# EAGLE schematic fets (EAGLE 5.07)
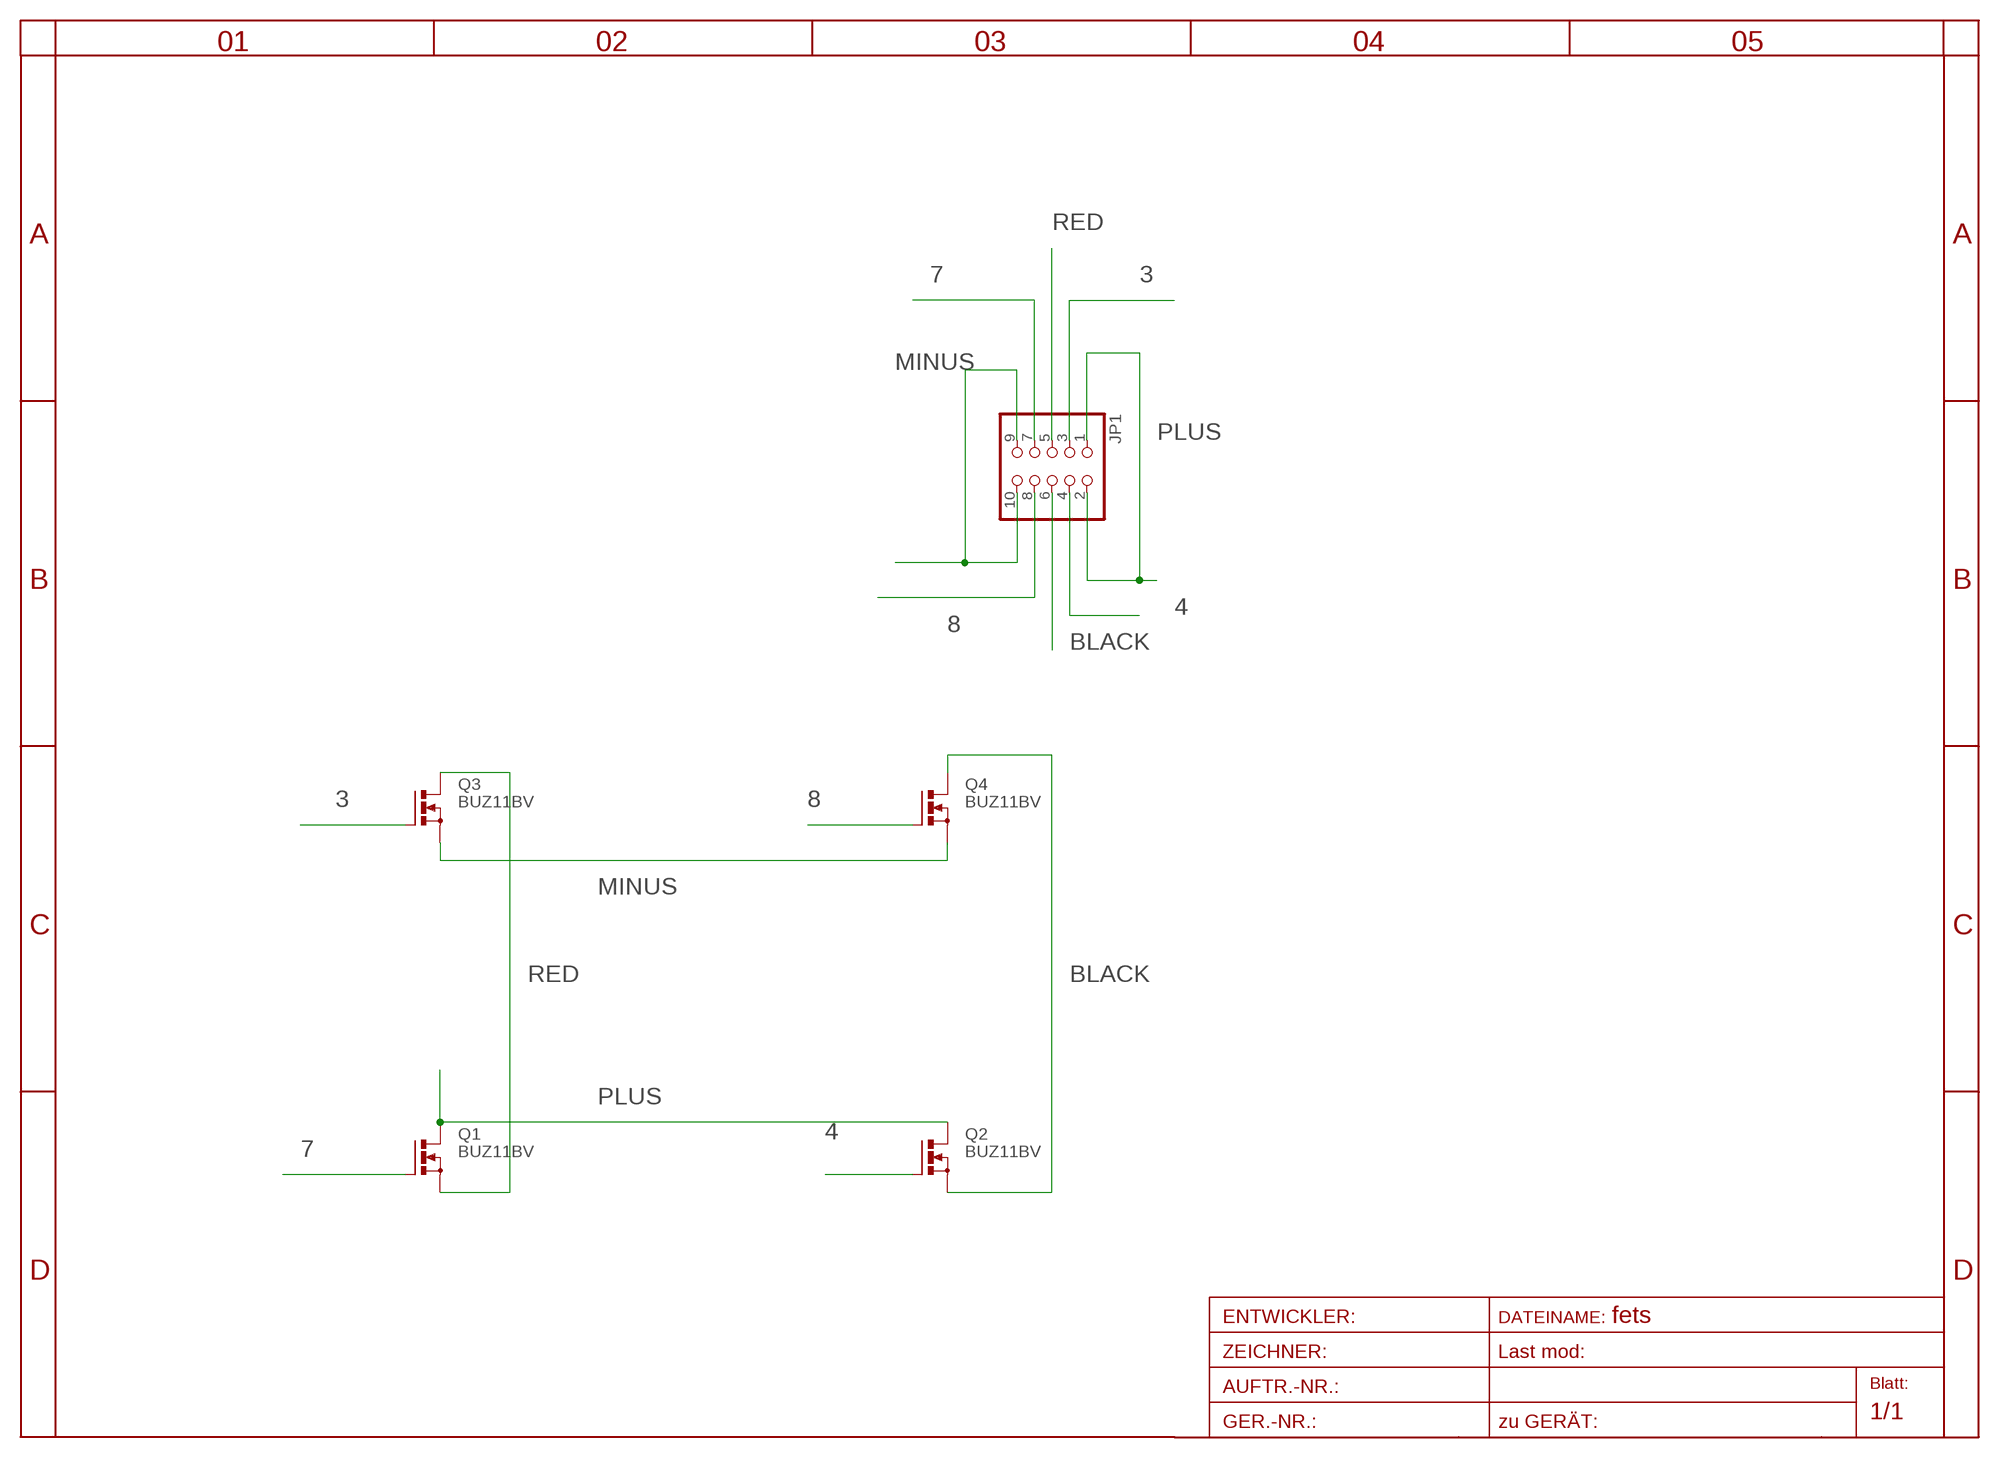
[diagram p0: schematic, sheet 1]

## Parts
JP1  PINHD-2X5  [2X05]
Q1  BUZ11BV  [TO220BV]
Q2  BUZ11BV  [TO220BV]
Q3  BUZ11BV  [TO220BV]
Q4  BUZ11BV  [TO220BV]

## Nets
3: JP1.3 Q3.G
4: JP1.4 Q2.G
7: JP1.7 Q1.G
8: JP1.8 Q4.G
BLACK: JP1.6 Q2.S Q4.D
MINUS: JP1.9 JP1.10 Q3.S Q4.S
PLUS: JP1.1 JP1.2 Q1.D Q2.D
RED: JP1.5 Q1.S Q3.D

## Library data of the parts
JP1 = pinhead:PINHD-2X5: PIN HEADER
Q1-Q4 = transistor-power:BUZ11: N-CHANNEL MOS FET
